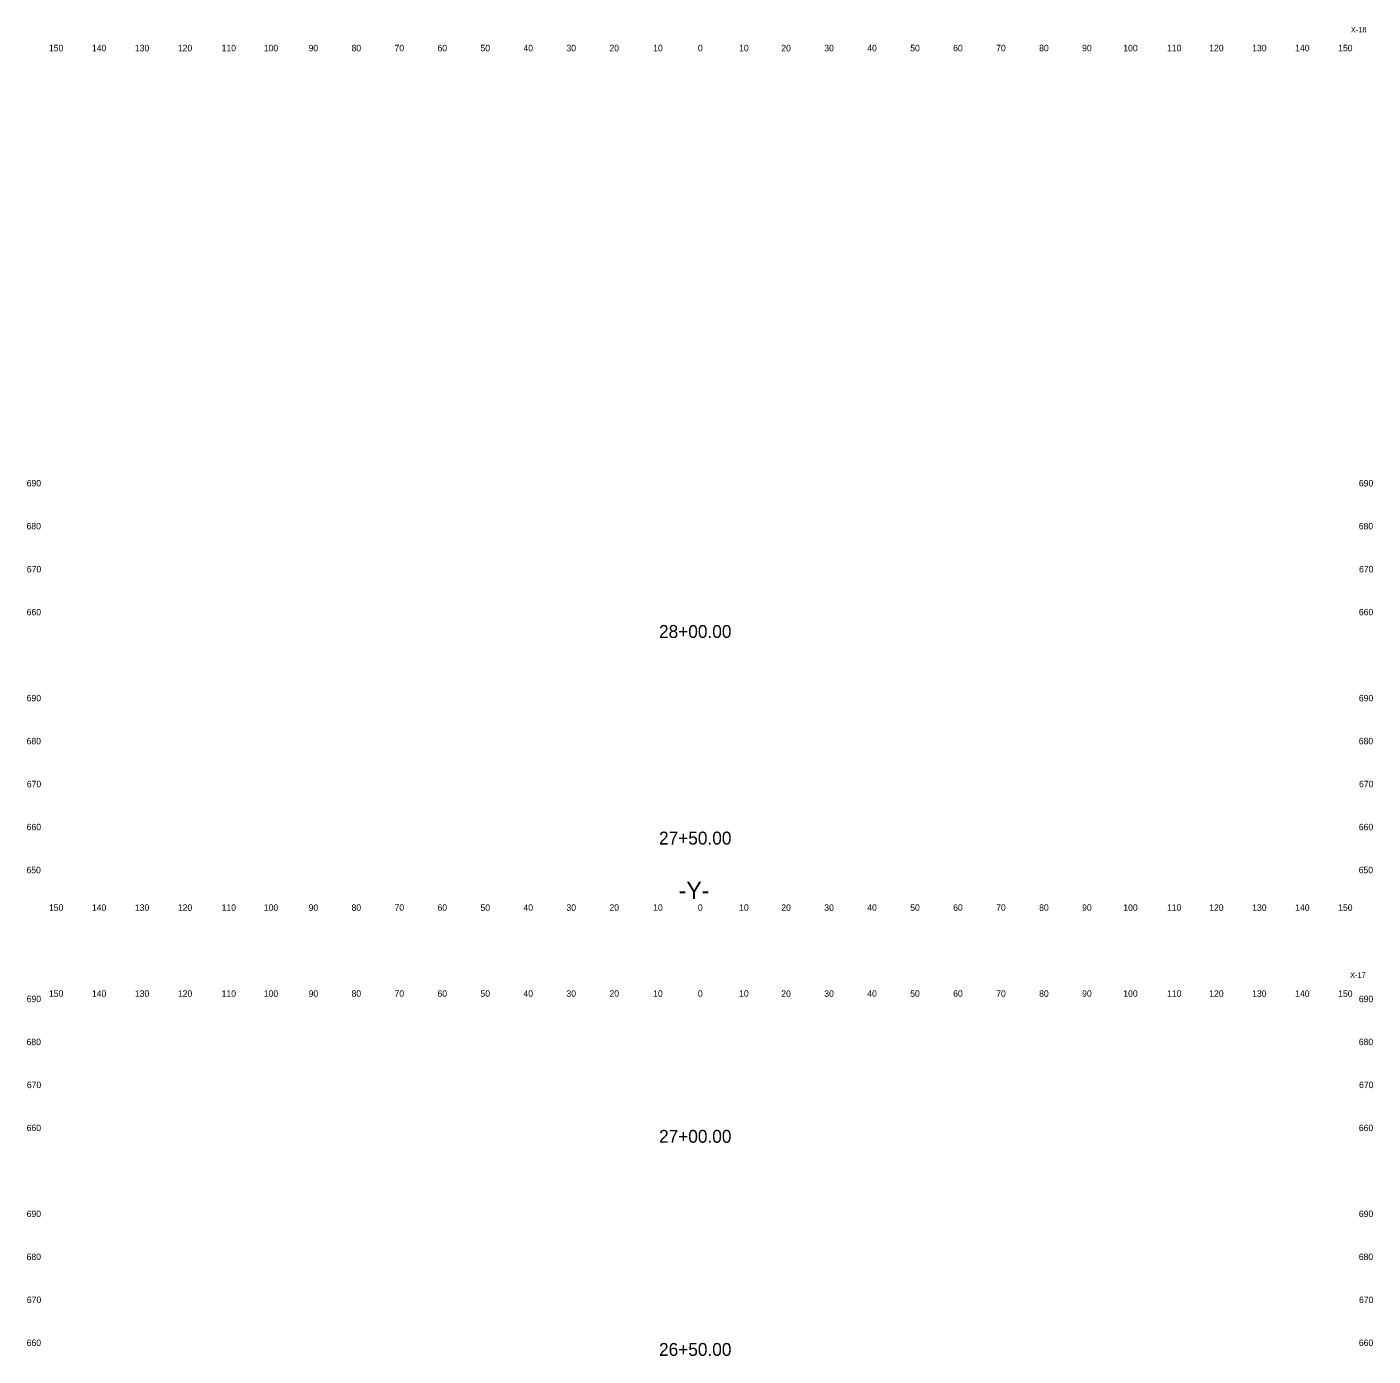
# Model space of a CAD drawing. Extents: x 3 to 317, y 1 to 1307.
# Drawn here: x 3.3 to 316.6, y 997.7 to 1306.9 of the extents above; entities that cross this region are included whole.
import ezdxf

# ---------------------------------------------------------------- set-up
doc = ezdxf.new("R2010")
doc.units = 0
for name, color, linetype in [('Prop XS Alignment Label', 7, 'Continuous'), ('Prop XS Elevation Labels', 7, 'Continuous'), ('Prop XS Offset Labels', 7, 'Continuous'), ('Prop XS Sheet Number', 7, 'Continuous'), ('Prop XS Station Labels', 7, 'Continuous')]:
    doc.layers.add(name, color=color, linetype=linetype)

msp = doc.modelspace()

# ---------------------------------------------------------------- texts
at = {"layer": 'Prop XS Alignment Label'}
msp.add_text('-Y-', height=4, dxfattribs=at).set_placement((155, 1104))
at = {"layer": 'Prop XS Elevation Labels'}
for s, p in [('690', (3.26, 1200)), ('690', (313.26, 1200)), ('680', (3.24, 1190)), ('680', (313.24, 1190)), ('670', (3.3, 1180)), ('670', (313.3, 1180)), ('660', (3.26, 1170)), ('660', (313.26, 1170)), ('690', (3.26, 1150)), ('690', (313.26, 1150)), ('680', (3.24, 1140)), ('680', (313.24, 1140)), ('670', (3.3, 1130)), ('670', (313.3, 1130)), ('660', (3.26, 1120)), ('660', (313.26, 1120)), ('650', (3.22, 1110)), ('650', (313.22, 1110)), ('690', (3.26, 1080)), ('690', (313.26, 1080)), ('680', (3.24, 1070)), ('680', (313.24, 1070)), ('670', (3.3, 1060)), ('670', (313.3, 1060)), ('660', (3.26, 1050)), ('660', (313.26, 1050)), ('690', (3.26, 1030)), ('690', (313.26, 1030)), ('680', (3.24, 1020)), ('680', (313.24, 1020)), ('670', (3.3, 1010)), ('670', (313.3, 1010)), ('660', (3.26, 1000)), ('660', (313.26, 1000))]:
    msp.add_text(s, height=1.5, dxfattribs=at).set_placement(p)
at = {"layer": 'Prop XS Offset Labels'}
for s, p in [('150', (8.44, 1301.25)), ('140', (18.44, 1301.25)), ('130', (28.44, 1301.25)), ('120', (38.44, 1301.25)), ('110', (48.62, 1301.25)), ('100', (58.44, 1301.25)), ('90', (68.86, 1301.25)), ('80', (78.86, 1301.25)), ('70', (88.86, 1301.25)), ('60', (98.86, 1301.25)), ('50', (108.86, 1301.25)), ('40', (118.86, 1301.25)), ('30', (128.86, 1301.25)), ('20', (138.86, 1301.25)), ('10', (149.04, 1301.25)), ('0', (159.45, 1301.25)), ('10', (169.04, 1301.25)), ('20', (178.86, 1301.25)), ('30', (188.86, 1301.25)), ('40', (198.86, 1301.25)), ('50', (208.86, 1301.25)), ('60', (218.86, 1301.25)), ('70', (228.86, 1301.25)), ('80', (238.86, 1301.25)), ('90', (248.86, 1301.25)), ('100', (258.44, 1301.25)), ('110', (268.62, 1301.25)), ('120', (278.44, 1301.25)), ('130', (288.44, 1301.25)), ('140', (298.44, 1301.25)), ('150', (308.44, 1301.25)), ('150', (8.44, 1101.25)), ('140', (18.44, 1101.25)), ('130', (28.44, 1101.25)), ('120', (38.44, 1101.25)), ('110', (48.62, 1101.25)), ('100', (58.44, 1101.25)), ('90', (68.86, 1101.25)), ('80', (78.86, 1101.25)), ('70', (88.86, 1101.25)), ('60', (98.86, 1101.25)), ('50', (108.86, 1101.25)), ('40', (118.86, 1101.25)), ('30', (128.86, 1101.25)), ('20', (138.86, 1101.25)), ('10', (149.04, 1101.25)), ('0', (159.45, 1101.25)), ('10', (169.04, 1101.25)), ('20', (178.86, 1101.25)), ('30', (188.86, 1101.25)), ('40', (198.86, 1101.25)), ('50', (208.86, 1101.25)), ('60', (218.86, 1101.25)), ('70', (228.86, 1101.25)), ('80', (238.86, 1101.25)), ('90', (248.86, 1101.25)), ('100', (258.44, 1101.25)), ('110', (268.62, 1101.25)), ('120', (278.44, 1101.25)), ('130', (288.44, 1101.25)), ('140', (298.44, 1101.25)), ('150', (308.44, 1101.25)), ('150', (8.44, 1081.25)), ('140', (18.44, 1081.25)), ('130', (28.44, 1081.25)), ('120', (38.44, 1081.25)), ('110', (48.62, 1081.25)), ('100', (58.44, 1081.25)), ('90', (68.86, 1081.25)), ('80', (78.86, 1081.25)), ('70', (88.86, 1081.25)), ('60', (98.86, 1081.25)), ('50', (108.86, 1081.25)), ('40', (118.86, 1081.25)), ('30', (128.86, 1081.25)), ('20', (138.86, 1081.25)), ('10', (149.04, 1081.25)), ('0', (159.45, 1081.25)), ('10', (169.04, 1081.25)), ('20', (178.86, 1081.25)), ('30', (188.86, 1081.25)), ('40', (198.86, 1081.25)), ('50', (208.86, 1081.25)), ('60', (218.86, 1081.25)), ('70', (228.86, 1081.25)), ('80', (238.86, 1081.25)), ('90', (248.86, 1081.25)), ('100', (258.44, 1081.25)), ('110', (268.62, 1081.25)), ('120', (278.44, 1081.25)), ('130', (288.44, 1081.25)), ('140', (298.44, 1081.25)), ('150', (308.44, 1081.25))]:
    msp.add_text(s, height=1.5, dxfattribs=at).set_placement(p)
at = {"layer": 'Prop XS Sheet Number'}
for s, p in [('X-18', (311.4, 1305.64)), ('X-17', (311.21, 1085.66))]:
    msp.add_text(s, height=1.25, dxfattribs=at).set_placement(p)
at = {"layer": 'Prop XS Station Labels'}
for s, p in [('28+00.00', (150.41, 1164.75)), ('27+50.00', (150.41, 1116.68)), ('27+00.00', (150.41, 1047.28)), ('26+50.00', (150.41, 997.7))]:
    msp.add_text(s, height=3, dxfattribs=at).set_placement(p)

doc.saveas('drawing.dxf')
